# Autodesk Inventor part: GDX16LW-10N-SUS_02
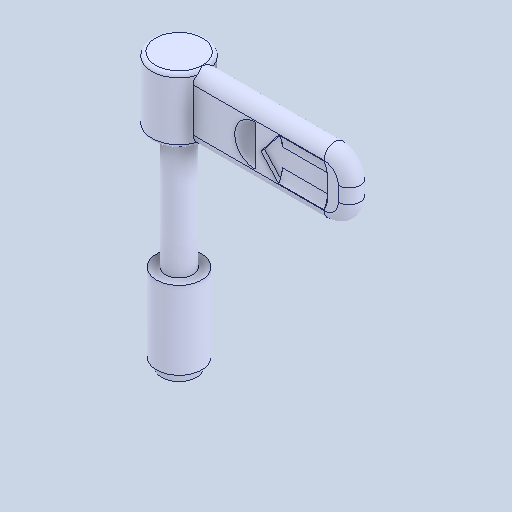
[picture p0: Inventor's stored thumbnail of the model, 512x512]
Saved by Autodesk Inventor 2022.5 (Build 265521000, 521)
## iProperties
Created: 2024-06
Part Number: GDX16LW-10N-SUS_02
Material: 一般
Document SubType Name: Modeling
Designer: ImaoCorp
Density: 1 g/cm^3
Appearance: 既定
Author: ImaoCorp
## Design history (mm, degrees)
feature "GDX16LW-10N-SUS_02"
node "ソリッド1"
